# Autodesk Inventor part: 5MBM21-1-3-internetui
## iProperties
Created: 2010-01
Part Number: 5MBM21-1-3-internetui
Document SubType Name: Modeling
Designer: Darius
Author: Darius
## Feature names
1. Base1
